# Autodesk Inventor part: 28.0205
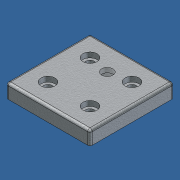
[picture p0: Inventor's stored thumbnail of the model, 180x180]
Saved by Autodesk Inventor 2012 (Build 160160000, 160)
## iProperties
Created: 2007-01
Part Number: 28.0205
Document SubType Name: Modeling
Designer: Andy Moles
Material: Aluminum-6061
Mass: 290.681 g
Surface Area: 236.286 cm^2
Volume: 107.262 cm^3
Density: 2.71 g/cm^3
Stock Number: 21.1059 B&T PLATE 90X90 GD
Description: BEARING PLATE 90X90 HANDWHEEL SIDE
Vendor: S
Author: Andy Moles
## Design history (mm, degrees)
sketch "Sketch1"
  geometry: L1 (-45, -45)-(45, -45); L2 (45, -45)-(45, 45); L3 (45, 45)-(-45, 45); L4 (-45, 45)-(-45, -45); L5 (-45, -45)-(45, 45); C1 r 4.5 at (-22.5, 22.5); C2 r 4.5 at (22.5, 22.5); C3 r 4.5 at (-22.5, -22.5); C4 r 4.5 at (22.5, -22.5); 2 further points
  constraints: 10 end point, 4 centre point, 2 parallel, 2 vertical alignment, 1 coincident, 1 horizontal, 1 midpoint, 1 perpendicular
  dimensions: "d0" = 90 distance of L2.end L3.end; "d1" = 90 distance of L3.end L1.start; "d2" = 9 diameter of C1; "d3" = 9 diameter of C2; "d4" = 22.5 distance from line of C1.centre L3; "d5" = 22.5 distance from line of L3 C2.centre; "d6" = 22.5 distance from line of C2.centre L2; "d7" = 22.5 distance from line of C1.centre L4; "d29" = 9 diameter of C3 (= d2); "d30" = 9 diameter of C4 (= d3); "d31" = 22.5 distance from line of C3.centre L1; "d32" = 22.5 distance from line of C4.centre L1
extrude "Extrusion1" new body sketch "Sketch1" distance "d8" = 15; taper "d9" = 0 deg
hole "Hole1" diameter "d12" = 15; stored, may be unused: countersink angle "d16" = 90 deg, drill point angle "d18" = 0 deg; dims "d10" = 10, "d11" = 10, "d13" = 6, "d14" = 4, "d15" = 2, "d17" = 5.5
hole "Hole2" diameter "d21" = 15; stored, may be unused: countersink angle "d25" = 90 deg, drill point angle "d27" = 0 deg; dims "d19" = 10, "d20" = 10, "d22" = 6, "d23" = 4, "d24" = 2, "d26" = 5.5
fillet "Fillet1" dims "d28" = 2.5
hole "Hole3" diameter "d35" = 15; stored, may be unused: countersink angle "d39" = 90 deg, drill point angle "d41" = 0 deg; dims "d33" = 10, "d34" = 10, "d36" = 6, "d37" = 4, "d38" = 2, "d40" = 5.5
hole "Hole4" diameter "d44" = 15; stored, may be unused: countersink angle "d48" = 90 deg, drill point angle "d50" = 0 deg; dims "d42" = 10, "d43" = 10, "d45" = 6, "d46" = 4, "d47" = 2, "d49" = 5.5
sketch "Sketch2"
  geometry: L1 (-45, -42.5)-(-45, 42.5) reference; L2 (-42.5, 45)-(42.5, 45) reference; C1 r 12 at (0, 18.5)
  constraints: 1 centre point
  dimensions: "d51" = 24 diameter of C1; "d73" = 45 distance from line of C1.centre L1; "d74" = 26.5 distance from line of C1.centre L2
extrude "Extrusion2" cut sketch "Sketch2" distance "d52" = 10; taper "d53" = 0 deg
hole "Hole5" diameter "d56" = 30; stored, may be unused: countersink angle "d60" = 90 deg, drill point angle "d62" = 0 deg; dims "d54" = 10, "d55" = 10, "d57" = 6, "d58" = 4, "d59" = 2, "d61" = 9
hole "Hole6" diameter "d65" = 12; stored, may be unused: countersink angle "d69" = 90 deg, drill point angle "d71" = 118 deg; dims "d63" = 10, "d64" = 10, "d66" = 6, "d67" = 4, "d68" = 2, "d70" = 8
body "Solid1"
